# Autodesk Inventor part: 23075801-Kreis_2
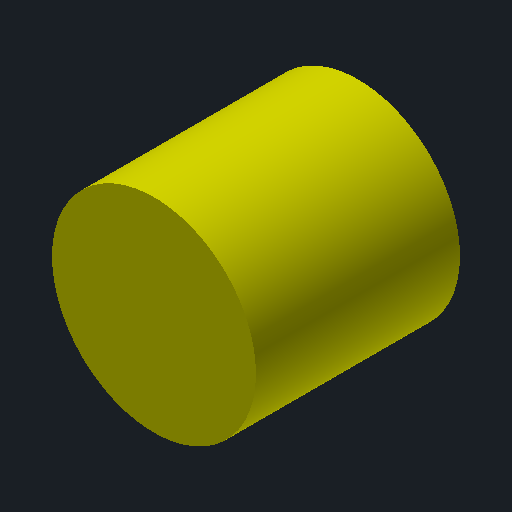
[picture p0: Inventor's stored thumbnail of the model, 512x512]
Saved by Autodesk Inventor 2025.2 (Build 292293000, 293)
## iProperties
Company: Ed. Züblin AG
Created: 2025-03
Part Number: 23075801-Kreis_2
Material: Stahlbeton C30/37
Document SubType Name: Modeling
Designer: FrodlSte
Mass: 1.9635e+06 g
Surface Area: 47123.9 cm^2
Volume: 785398 cm^3
Density: 2.5 g/cm^3
Appearance: Beton C30/37
Description: Abdichtungstraeger
z_Bereich: Tunnelbau
z_Direktion: Tief- und Tunnelbau
z_Konzerneinheit: Zentrale Technik
z_Matchkey: =<z_Matchkey_010>_<z_Matchkey_020>_<z_Matchkey_030>_<z_Matchkey_040>_<z_Matchkey_050>_<z_Matchkey_060>_<z_Matchkey_070>_<z_Matchkey_080>_<z_Matchkey_090>_<z_Mat
cpiComponentType: Attribut
cpiFitMatchkey: =<z_Matchkey>
z_Matchkey_010: xxxxx
z_Matchkey_020: 5DTUB
z_Matchkey_030: xxx
z_Matchkey_040: xxx
z_Matchkey_050: xxx
z_Matchkey_060: xxx
z_Matchkey_070: xxx
z_Matchkey_080: xxx
z_Matchkey_090: xxx
z_Matchkey_100: xxx
z_Matchkey_110: xxx
z_Matchkey_120: xxxxxxx
z_Matchkey_130: STRO
z_Matchkey_140: LAIB
DocNumber: 23075801-Kreis_2.ipt
Folder: DL23075801-DE-Pfaffensteigtunnel\BIM\Testmodell
VDS_Category: 09 - BIM - Konstruktion
DBSet_Beton:Betondeckung_mm: -9999,900000000001
DBSet_Beton:Betonstahlguete: BST_500A
DBSet_Beton:Bewehrungsgehalt: -99999.0
DBSet_Beton:Druckfestigkeitsklasse: C12/15
DBSet_Beton:Expositionsklasse_X: ND
DBSet_Beton:Expositionsklasse_XA: ND
DBSet_Beton:Expositionsklasse_XC: ND
DBSet_Beton:Expositionsklasse_XD: ND
DBSet_Beton:Expositionsklasse_XF: ND
DBSet_Beton:Expositionsklasse_XM: ND
DBSet_Beton:Expositionsklasse_XS: ND
DBSet_Beton:Feuchtigkeitsklasse: ND
DBSet_Beton:Groesstkorn: 11
DBSet_Beton:Herstellungsort: FTB
DBSet_Beton:Luftporenbeton: ND
DBSet_Beton:PP_Faser: False
DBSet_Beton:PP_Faser_Gehalt: -99999.0
DBSet_Beton:Rohdichte: -99999.0
DBSet_Beton:Sichtbetonklasse: ND
DBSet_Beton:Unbewehrter_Beton: False
DBSet_Beton:Wasserzementwert_max: -99999.0
DBSet_Beton:WU_Beton: False
DBSet_Beton:Zusatzmittel: ND
DBSet_Element:010_Eigentuemer: DBE
DBSet_Element:020_Autor: ND
DBSet_Element:030_Projektnummer: G.016268527
DBSet_Element:040_Bereich: ND
DBSet_Element:050_Vertragspartner: ND
DBSet_Element:060_Gewerk: ND
DBSet_Element:070_Bauwerk: EW
DBSet_Element:080_Bauwerksnummer: 17030
DBSet_Element:090_Bezeichnung: ND
DBSet_Element:100_Gruppe: Abdichtung
DBSet_Element:110_Element: Abdichtungstraeger
DBSet_Element:120_Elementtyp: ND
DBSet_Element:130_Identifikationsnummer: ND
DBSet_Element:140_Position_1: KALO
DBSet_Element:150_Position_2: FIRS
DBSet_Element:160_PUID: ND
DBSet_Element:170_Hauptmaterialitaet: Baugrund
DBSet_Element:171_Materialindikator_1: ND
DBSet_Element:172_Materialindikator_2: ND
DBSet_Geometrie:Dicke: -99999.0
DBSet_Geometrie:Flaeche: -99999.0
DBSet_Geometrie:Volumen_Solid: 7.21
DBSet_Position:Streckenachse: ND
DBSet_Position:Streckenkilometer_Anfang: -99999
DBSet_Position:Streckenkilometer_Ende: -99999
DBSet_Position:Tunnelachse: ND
DBSet_Position:Tunnelmeter_Anfang: -99999
DBSet_Position:Tunnelmeter_Ende: -99999
DBSet_TP:Status: ABB
z_DBSet_Beton:Betondeckung_mm: -99999,000 mm
z_DBSet_Beton:Betonstahlguete: Nicht definiert
z_DBSet_Beton:Bewehrungsgehalt: -99999,000 oE
z_DBSet_Beton:Druckfestigkeitsklasse: Beton C25/30
z_DBSet_Beton:Expositionsklasse_X: Nicht definiert
z_DBSet_Beton:Expositionsklasse_XA: Nicht definiert
z_DBSet_Beton:Expositionsklasse_XC: Nicht definiert
z_DBSet_Beton:Expositionsklasse_XD: Nicht definiert
z_DBSet_Beton:Expositionsklasse_XF: Nicht definiert
z_DBSet_Beton:Expositionsklasse_XM: Nicht definiert
z_DBSet_Beton:Expositionsklasse_XS: Nicht definiert
z_DBSet_Beton:Feuchtigkeitsklasse: Nicht definiert
z_DBSet_Beton:Groesstkorn: 8 mm
z_DBSet_Beton:Herstellungsort: Spritzbeton
z_DBSet_Beton:Luftporenbeton: nicht definiert
z_DBSet_Beton:PP_Faser: Falsch
z_DBSet_Beton:PP_Faser_Gehalt: -99999,000 oE
z_DBSet_Beton:Rohdichte: -99999,000 oE
z_DBSet_Beton:Sichtbetonklasse: Nicht definiert
z_DBSet_Beton:Unbewehrter_Beton: Falsch
z_DBSet_Beton:Wasserzementwert_max: -99999,000 oE
z_DBSet_Beton:WU_Beton: Falsch
z_DBSet_Beton:Zusatzmittel: nicht definiert
z_DBSet_Element:010_Eigentuemer: DBInfraGo
z_DBSet_Element:020_Autor: Vertragspartner 2 ZB
z_DBSet_Element:030_Projektnummer: Gaeubahn Nord HP Goldberg (DBnfraGO, BK11)
z_DBSet_Element:040_Bereich: PFA 1 Tunnel
z_DBSet_Element:050_Vertragspartner: Tunnel
z_DBSet_Element:060_Gewerk: Tunnelbau
z_DBSet_Element:070_Bauwerk: SBW-Tu
z_DBSet_Element:080_Bauwerksnummer: zzz (leer)
z_DBSet_Element:090_Bezeichnung: zzz (leer)
z_DBSet_Element:100_Gruppe: Abdichtung
z_DBSet_Element:110_Element: Abdichtungstraeger
z_DBSet_Element:120_Elementtyp: Abdichtungstraeger
z_DBSet_Element:130_Identifikationsnummer: Nicht definiert
z_DBSet_Element:140_Position_1: Strosse
z_DBSet_Element:150_Position_2: Nicht definiert
z_DBSet_Element:160_PUID: Nicht definiert
z_DBSet_Element:170_Hauptmaterialitaet: Beton
z_DBSet_Element:171_Materialindikator_1: Spritzbeton
z_DBSet_Element:172_Materialindikator_2: Nicht definiert
z_DBSet_Geometrie:Dicke: 0,020 m
z_DBSet_Geometrie:Flaeche: -99999,000 m^2
z_DBSet_Position:Streckenachse: zzz (leer)
z_DBSet_Position:Streckenkilometer_Anfang: -11111,000 oE
z_DBSet_Position:Streckenkilometer_Ende: -11111,000 oE
z_DBSet_Position:Tunnelachse: zzz (leer)
z_DBSet_Position:Tunnelmeter_Anfang: -11111,000 oE
z_DBSet_Position:Tunnelmeter_Ende: -11111,000 oE
z_DBSet_TP:Status: Neubau
z_DBSet_Geometrie:Volumen_Solid: -11111,000 m^3
Author: FrodlSte
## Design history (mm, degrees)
derived "23075801-Skelett.ipt"
node "Kreis_2"
node "Volumenkörpern"
node "Oberflächenkörpern"
feature "Kreis_2::23075801-Skelett.ipt" dims "d4" = 10
tag "Bezeichnung1"
